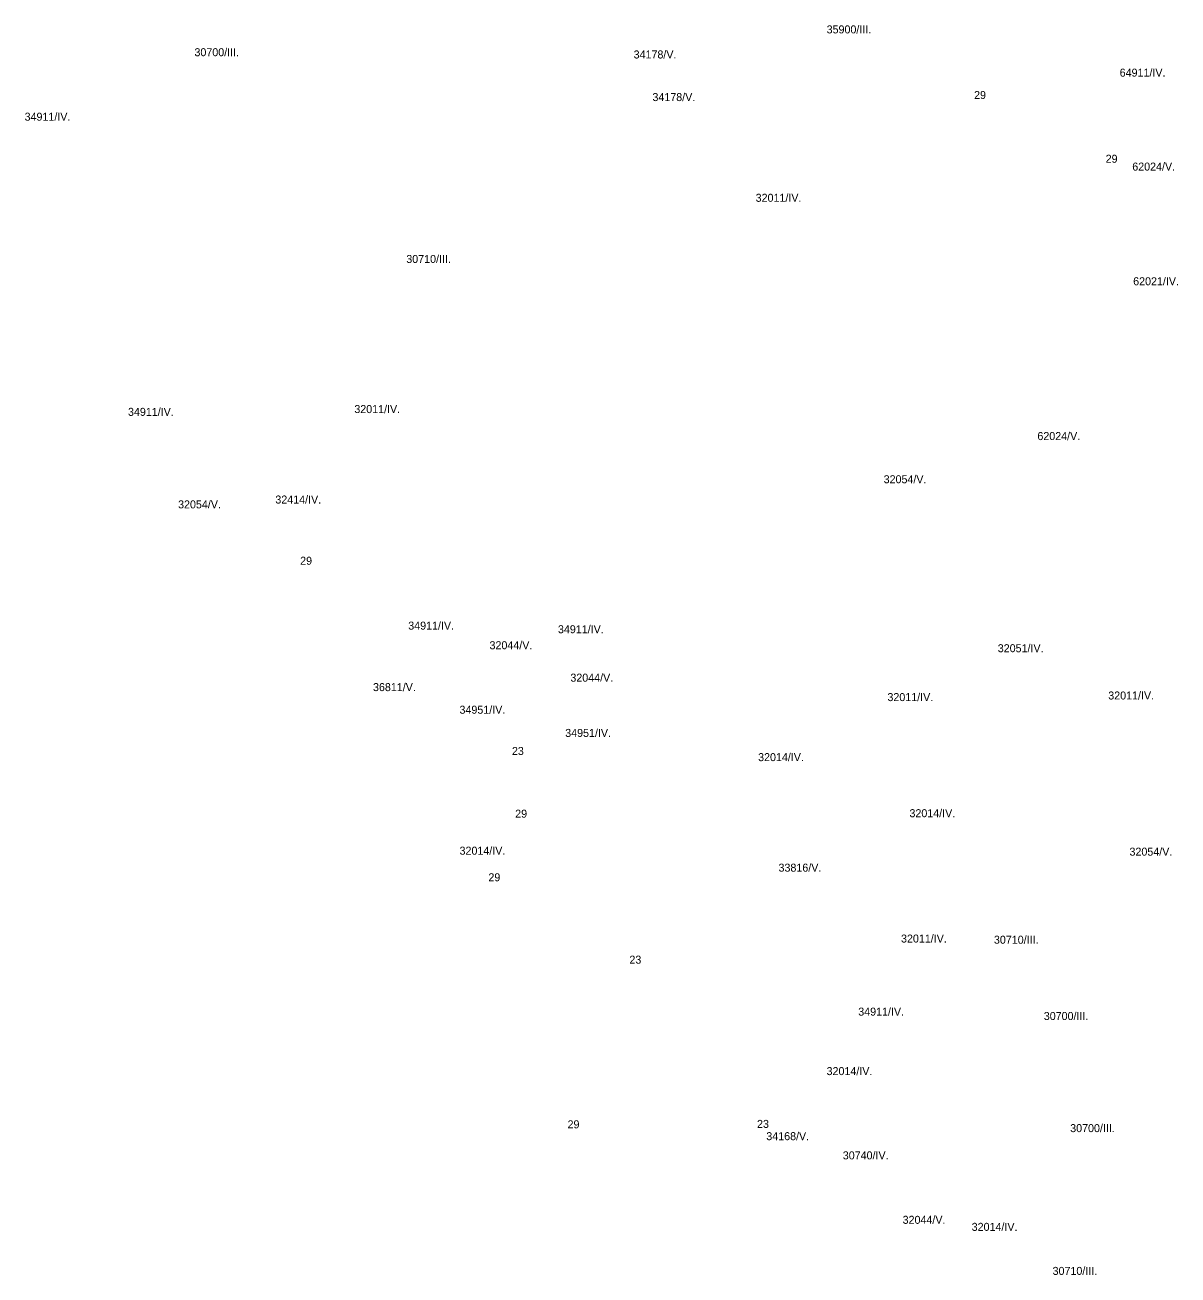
# Model space of a CAD drawing. Extents: x -521579 to -516881, y -1190081 to -1185166.
# Drawn here: x -521452 to -519290, y -1189969 to -1187626 of the extents above; entities that cross this region are included whole.
import ezdxf

# ---------------------------------------------------------------- set-up
doc = ezdxf.new("R2010")
doc.units = 0
doc.layers.add('BPEJ_s', color=7, linetype='Continuous')

msp = doc.modelspace()

# ---------------------------------------------------------------- texts
at = {"layer": 'BPEJ_s'}
for s, p in [('35900/III.', (-519948.5, -1187641.3)), ('30700/III.', (-521133.9, -1187684.1)), ('34178/V.', (-520310.4, -1187688.3)), ('64911/IV.', (-519399, -1187722.4)), ('34178/V.', (-520275.1, -1187768.2)), ('29', (-519672, -1187764.3)), ('34911/IV.', (-521452.4, -1187805)), ('29', (-519425.3, -1187883.8)), ('62024/V.', (-519375.4, -1187898.5)), ('32011/IV.', (-520081.6, -1187957)), ('30710/III.', (-520736.7, -1188071.7)), ('62021/IV.', (-519373.7, -1188113.5)), ('34911/IV.', (-521258.5, -1188358.3)), ('32011/IV.', (-520834.1, -1188353.1)), ('62024/V.', (-519553.3, -1188403.7)), ('32054/V.', (-519841.6, -1188484.7)), ('32054/V.', (-521164.6, -1188531.8)), ('32414/IV.', (-520982.2, -1188522.7)), ('29', (-520935.7, -1188637.5)), ('34911/IV.', (-520733, -1188759.1)), ('34911/IV.', (-520452.3, -1188765.9)), ('32044/V.', (-520580.6, -1188795.9)), ('32051/IV.', (-519627.6, -1188801.5)), ('32044/V.', (-520429, -1188856.7)), ('36811/V.', (-520799.1, -1188874.4)), ('32011/IV.', (-519834.5, -1188893.1)), ('32011/IV.', (-519420.4, -1188890.1)), ('34951/IV.', (-520636.9, -1188916.8)), ('34951/IV.', (-520438.7, -1188960.3)), ('23', (-520538.6, -1188994.1)), ('32014/IV.', (-520077, -1189005.7)), ('29', (-520532.5, -1189111.7)), ('32014/IV.', (-519793.2, -1189110.8)), ('32014/IV.', (-520636.8, -1189181.1)), ('32054/V.', (-519380.6, -1189182.9)), ('33816/V.', (-520038.7, -1189212.9)), ('29', (-520582.7, -1189230.9)), ('32011/IV.', (-519809, -1189345.8)), ('30710/III.', (-519634.8, -1189348)), ('23', (-520318.3, -1189385.4)), ('34911/IV.', (-519889.2, -1189482.8)), ('30700/III.', (-519541.3, -1189491)), ('32014/IV.', (-519948.6, -1189594.3)), ('29', (-520434.3, -1189694.1)), ('23', (-520079, -1189693.3)), ('30700/III.', (-519491.8, -1189701.2)), ('34168/V.', (-520061.6, -1189716.3)), ('30740/IV.', (-519918.2, -1189752.3)), ('32044/V.', (-519806, -1189873.1)), ('32014/IV.', (-519676.5, -1189886.3)), ('30710/III.', (-519524.8, -1189968.9))]:
    msp.add_text(s, height=15, dxfattribs=at).set_placement(p)

doc.saveas('drawing.dxf')
